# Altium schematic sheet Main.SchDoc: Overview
size A4; Organization: Trenz Electronic GmbH; DocumentNumber: TE0304 - Demo Baseboard; Revision: 00; SheetNumber: 1; SheetTotal: 4; Date: 2009-04-16
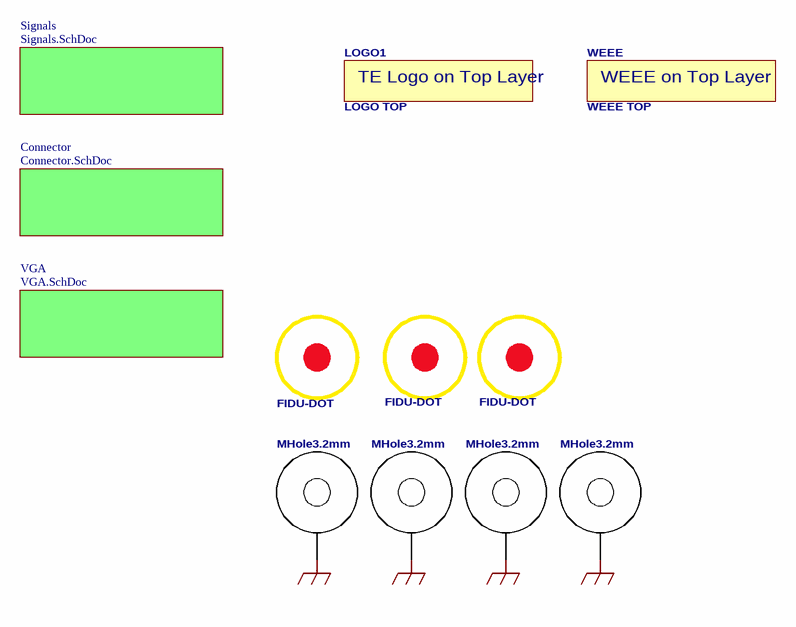
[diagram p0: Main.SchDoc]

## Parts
H1  MHole3.2mm  [MHole3_2mm]  (no BOM)
H2  MHole3.2mm  [MHole3_2mm]  (no BOM)
H3  MHole3.2mm  [MHole3_2mm]  (no BOM)
H4  MHole3.2mm  [MHole3_2mm]  (no BOM)
LOGO1  LOGO TOP  [Logo Top]  (no BOM)
PM1  FIDU-DOT  [FIDU-DOT]
PM2  FIDU-DOT  [FIDU-DOT]
PM3  FIDU-DOT  [FIDU-DOT]
WEEE  WEEE TOP  [WEEETOP_10_25mm]  (no BOM)

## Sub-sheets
Connector = Connector.SchDoc: no entries
Signals = Signals.SchDoc: no entries
VGA = VGA.SchDoc: no entries

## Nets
FGND: H1.1 H2.1 H3.1 H4.1

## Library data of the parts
H1-H4 = 22898: AN: 22898
LOGO1 = 22901: AN: 22901
PM1-PM3 = 22906: AN: 22906
WEEE = 22300: AN: 22300; Bezeichnung: WEEE TOP (10.25mm)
